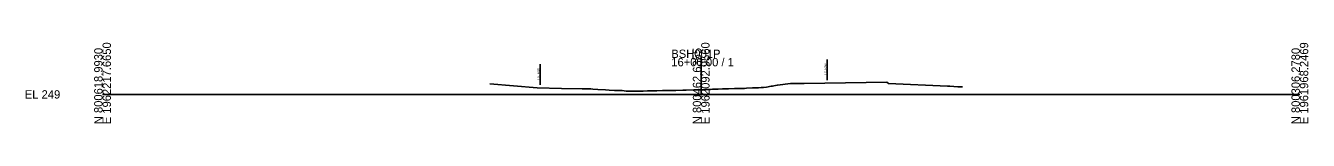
# Model space of a CAD drawing. Extents: x -26 to 1403, y -10 to 19587.
# Drawn here: x -25.7 to 402.8, y -9.7 to 17.3 of the extents above; entities that cross this region are included whole.
import ezdxf

# ---------------------------------------------------------------- set-up
doc = ezdxf.new("R2010")
doc.units = 0
for name, color, linetype in [('Default', 7, 'Continuous'), ('RD_GPK_XS_Cell', 7, 'Continuous'), ('RD_XS_ExGround', 7, 'Continuous'), ('RD_XS_ExRW', 7, 'Continuous'), ('RD_XS_TX_Elev_EX', 7, 'Continuous')]:
    doc.layers.add(name, color=color, linetype=linetype)

msp = doc.modelspace()

# ---------------------------------------------------------------- linework, layer by layer
at = {"layer": 'RD_GPK_XS_Cell'}
for p, q in [((200, 0), (200, 12.23)), ((0, 0), (200, 0)), ((200, 0), (400, 0))]:
    msp.add_line(p, q, dxfattribs=at)
at = {"layer": 'RD_XS_ExGround'}
msp.add_lwpolyline([(129.36, 3.51), (145.15, 2.18), (153.35, 2.03), (160.21, 1.86), (161.14, 1.86), (161.95, 1.85), (163.11, 1.82), (163.8, 1.8), (165.47, 1.69), (168.06, 1.53), (169.26, 1.45), (171.03, 1.33), (171.94, 1.26), (172.3, 1.27), (172.74, 1.33), (173.12, 1.31), (173.6, 1.27), (174.98, 1.11), (175.95, 1.05), (178.97, 1.1), (180.56, 1.12), (182.02, 1.15), (182.48, 1.16), (183.05, 1.18), (185.21, 1.24), (187.04, 1.28), (188.38, 1.3), (189.57, 1.32), (191.02, 1.34), (191.58, 1.36), (193.87, 1.42), (195.02, 1.46), (197.57, 1.54), (197.91, 1.55), (198.33, 1.55), (199.08, 1.56), (200, 1.58), (201.2, 1.61), (203.12, 1.67), (203.82, 1.7), (204.4, 1.72), (205.64, 1.76), (207.15, 1.81), (207.55, 1.82), (209.15, 1.88), (211.12, 1.94), (213.96, 2.02), (214.48, 2.03), (215.12, 2.06), (217.16, 2.15), (218.03, 2.19), (219.15, 2.24), (220.05, 2.28), (220.85, 2.32), (221.78, 2.47), (223.34, 2.71), (223.81, 2.79), (224.21, 2.85), (224.84, 2.96), (225.4, 3.05), (225.52, 3.04), (229.82, 3.62), (234.41, 3.62), (261.99, 4.08), (262.57, 3.61), (282.26, 2.75), (283.1, 2.71), (285.73, 2.58), (287.35, 2.5)], dxfattribs=at)
at = {"layer": 'RD_XS_ExRW'}
for p, q in [((146.22, 3.16), (146.22, 10.16)), ((242.1, 4.75), (242.1, 11.75))]:
    msp.add_line(p, q, dxfattribs=at)

# ---------------------------------------------------------------- texts
at = {"layer": 'Default'}
msp.add_text('-', height=0.0001, dxfattribs=at).set_placement((0, 0))
at = {"layer": 'RD_GPK_XS_Cell'}
for s, p in [('E 1962217.6650', (2.8, -10)), ('E 1962092.9560', (202.8, -10)), ('E 1961968.2469', (402.8, -10)), ('N 800618.9930', (0, -10)), ('N 800462.6355', (200, -10)), ('N 800306.2780', (400, -10))]:
    msp.add_text(s, height=2.8, rotation=90, dxfattribs=at).set_placement(p)
for s, p in [('BSH001P', (190, 12.23)), ('16+00.00 / 1', (190, 9.43)), ('EL 249', (-26, -1.4))]:
    msp.add_text(s, height=2.8, dxfattribs=at).set_placement(p)
at = {"layer": 'RD_XS_ExRW'}
for p in [(145.97, 4.83), (241.85, 6.42)]:
    msp.add_text('EX. R/W ', height=0.75, rotation=90, dxfattribs=at).set_placement(p)
at = {"layer": 'RD_XS_TX_Elev_EX'}
msp.add_text('250.58', height=1, dxfattribs=at).set_placement((197.95, -0.92))

doc.saveas('drawing.dxf')
